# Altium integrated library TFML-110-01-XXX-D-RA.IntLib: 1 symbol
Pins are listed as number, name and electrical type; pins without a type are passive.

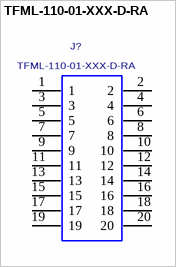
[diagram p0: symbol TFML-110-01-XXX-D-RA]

## TFML-110-01-XXX-D-RA
designator J?
0.050" SHROUDEDTERMINAL STRIP, 20 PINS.; MANUFACTURER: SAMTEC
footprint TFML-110-01-XXX-D-RA
pins: 1, 2, 3, 4, 5, 6, 7, 8, 9, 10, 11, 12, 13, 14, 15, 16, 17, 18, 19, 20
